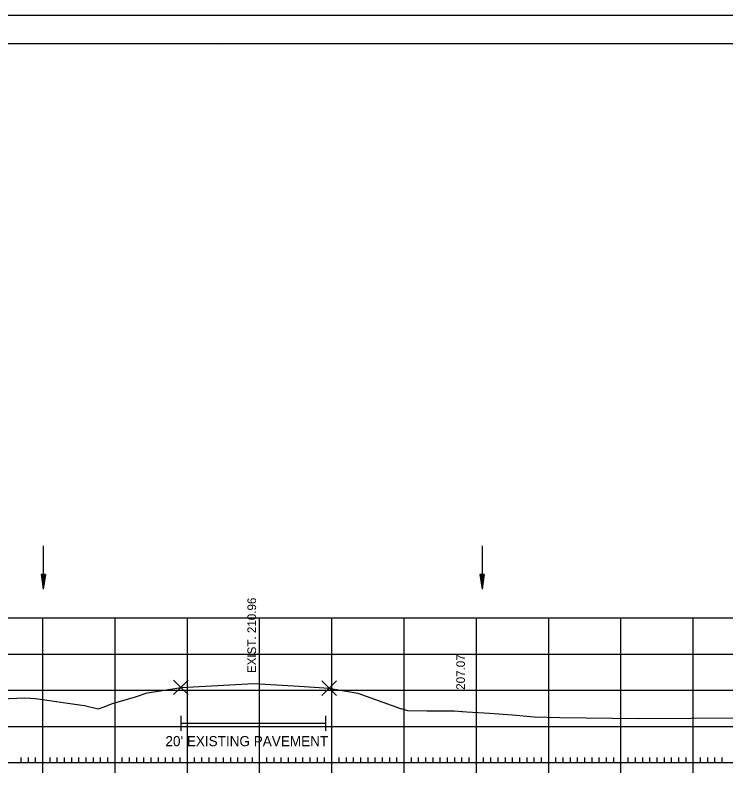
# Model space of a CAD drawing. Extents: x 1312042 to 1371461, y 379929 to 1834241.
# Drawn here: x 1371264.5 to 1371362.8, y 380250.2 to 380355.6 of the extents above; entities that cross this region are included whole.
import ezdxf

# ---------------------------------------------------------------- set-up
doc = ezdxf.new("R2010")
doc.units = 0
for name, color, linetype in [('Default', 7, 'Continuous'), ('R_Axis', 7, 'Continuous'), ('R_Axis Annot', 7, 'Continuous'), ('R_Border', 7, 'Continuous'), ('R_Exist Surface', 7, 'Continuous'), ('R_Grid', 7, 'Continuous'), ('R_No Plot', 7, 'Continuous'), ('R_Water Annot', 7, 'Continuous'), ('R_Xsect Elev', 7, 'Continuous')]:
    doc.layers.add(name, color=color, linetype=linetype)

msp = doc.modelspace()

# ---------------------------------------------------------------- linework, layer by layer
at = {"layer": 'Default'}
for p, q in [((1371287.38, 380258.72), (1371287.38, 380256.66)), ((1371307.38, 380258.72), (1371307.38, 380256.66)), ((1371287.38, 380257.69), (1371307.38, 380257.69))]:
    msp.add_line(p, q, dxfattribs=at)
at = {"layer": 'R_Axis'}
for p, q in [((1371268.28, 380250.85), (1371268.28, 380253.65)), ((1371278.28, 380250.85), (1371278.28, 380253.65)), ((1371288.28, 380250.85), (1371288.28, 380253.65)), ((1371298.28, 380250.85), (1371298.28, 380253.65)), ((1371308.28, 380250.85), (1371308.28, 380253.65)), ((1371318.28, 380250.85), (1371318.28, 380253.65)), ((1371328.28, 380250.85), (1371328.28, 380253.65)), ((1371338.28, 380250.85), (1371338.28, 380253.65)), ((1371348.28, 380250.85), (1371348.28, 380253.65)), ((1371358.28, 380250.85), (1371358.28, 380253.65)), ((1371158.28, 380252.25), (1371438.28, 380252.25)), ((1371265.28, 380252.25), (1371265.28, 380252.95)), ((1371266.28, 380252.25), (1371266.28, 380252.95)), ((1371267.28, 380252.25), (1371267.28, 380252.95)), ((1371269.28, 380252.25), (1371269.28, 380252.95)), ((1371270.28, 380252.25), (1371270.28, 380252.95)), ((1371271.28, 380252.25), (1371271.28, 380252.95)), ((1371272.28, 380252.25), (1371272.28, 380252.95)), ((1371273.28, 380252.25), (1371273.28, 380252.95)), ((1371274.28, 380252.25), (1371274.28, 380252.95)), ((1371275.28, 380252.25), (1371275.28, 380252.95)), ((1371276.28, 380252.25), (1371276.28, 380252.95)), ((1371277.28, 380252.25), (1371277.28, 380252.95)), ((1371279.28, 380252.25), (1371279.28, 380252.95)), ((1371280.28, 380252.25), (1371280.28, 380252.95)), ((1371281.28, 380252.25), (1371281.28, 380252.95)), ((1371282.28, 380252.25), (1371282.28, 380252.95)), ((1371283.28, 380252.25), (1371283.28, 380252.95)), ((1371284.28, 380252.25), (1371284.28, 380252.95)), ((1371285.28, 380252.25), (1371285.28, 380252.95)), ((1371286.28, 380252.25), (1371286.28, 380252.95)), ((1371287.28, 380252.25), (1371287.28, 380252.95)), ((1371289.28, 380252.25), (1371289.28, 380252.95)), ((1371290.28, 380252.25), (1371290.28, 380252.95)), ((1371291.28, 380252.25), (1371291.28, 380252.95)), ((1371292.28, 380252.25), (1371292.28, 380252.95)), ((1371293.28, 380252.25), (1371293.28, 380252.95)), ((1371294.28, 380252.25), (1371294.28, 380252.95)), ((1371295.28, 380252.25), (1371295.28, 380252.95)), ((1371296.28, 380252.25), (1371296.28, 380252.95)), ((1371297.28, 380252.25), (1371297.28, 380252.95)), ((1371299.28, 380252.25), (1371299.28, 380252.95)), ((1371300.28, 380252.25), (1371300.28, 380252.95)), ((1371301.28, 380252.25), (1371301.28, 380252.95)), ((1371302.28, 380252.25), (1371302.28, 380252.95)), ((1371303.28, 380252.25), (1371303.28, 380252.95)), ((1371304.28, 380252.25), (1371304.28, 380252.95)), ((1371305.28, 380252.25), (1371305.28, 380252.95)), ((1371306.28, 380252.25), (1371306.28, 380252.95)), ((1371307.28, 380252.25), (1371307.28, 380252.95)), ((1371309.28, 380252.25), (1371309.28, 380252.95)), ((1371310.28, 380252.25), (1371310.28, 380252.95)), ((1371311.28, 380252.25), (1371311.28, 380252.95)), ((1371312.28, 380252.25), (1371312.28, 380252.95)), ((1371313.28, 380252.25), (1371313.28, 380252.95)), ((1371314.28, 380252.25), (1371314.28, 380252.95)), ((1371315.28, 380252.25), (1371315.28, 380252.95)), ((1371316.28, 380252.25), (1371316.28, 380252.95)), ((1371317.28, 380252.25), (1371317.28, 380252.95)), ((1371319.28, 380252.25), (1371319.28, 380252.95)), ((1371320.28, 380252.25), (1371320.28, 380252.95)), ((1371321.28, 380252.25), (1371321.28, 380252.95)), ((1371322.28, 380252.25), (1371322.28, 380252.95)), ((1371323.28, 380252.25), (1371323.28, 380252.95)), ((1371324.28, 380252.25), (1371324.28, 380252.95)), ((1371325.28, 380252.25), (1371325.28, 380252.95)), ((1371326.28, 380252.25), (1371326.28, 380252.95)), ((1371327.28, 380252.25), (1371327.28, 380252.95)), ((1371329.28, 380252.25), (1371329.28, 380252.95)), ((1371330.28, 380252.25), (1371330.28, 380252.95)), ((1371331.28, 380252.25), (1371331.28, 380252.95)), ((1371332.28, 380252.25), (1371332.28, 380252.95)), ((1371333.28, 380252.25), (1371333.28, 380252.95)), ((1371334.28, 380252.25), (1371334.28, 380252.95)), ((1371335.28, 380252.25), (1371335.28, 380252.95)), ((1371336.28, 380252.25), (1371336.28, 380252.95)), ((1371337.28, 380252.25), (1371337.28, 380252.95)), ((1371339.28, 380252.25), (1371339.28, 380252.95)), ((1371340.28, 380252.25), (1371340.28, 380252.95)), ((1371341.28, 380252.25), (1371341.28, 380252.95)), ((1371342.28, 380252.25), (1371342.28, 380252.95)), ((1371343.28, 380252.25), (1371343.28, 380252.95)), ((1371344.28, 380252.25), (1371344.28, 380252.95)), ((1371345.28, 380252.25), (1371345.28, 380252.95)), ((1371346.28, 380252.25), (1371346.28, 380252.95)), ((1371347.28, 380252.25), (1371347.28, 380252.95)), ((1371349.28, 380252.25), (1371349.28, 380252.95)), ((1371350.28, 380252.25), (1371350.28, 380252.95)), ((1371351.28, 380252.25), (1371351.28, 380252.95)), ((1371352.28, 380252.25), (1371352.28, 380252.95)), ((1371353.28, 380252.25), (1371353.28, 380252.95)), ((1371354.28, 380252.25), (1371354.28, 380252.95)), ((1371355.28, 380252.25), (1371355.28, 380252.95)), ((1371356.28, 380252.25), (1371356.28, 380252.95)), ((1371357.28, 380252.25), (1371357.28, 380252.95)), ((1371359.28, 380252.25), (1371359.28, 380252.95)), ((1371360.28, 380252.25), (1371360.28, 380252.95)), ((1371361.28, 380252.25), (1371361.28, 380252.95)), ((1371362.28, 380252.25), (1371362.28, 380252.95))]:
    msp.add_line(p, q, dxfattribs=at)
at = {"layer": 'R_Border'}
for p, q in [((1371140.28, 380351.71), (1371456.46, 380351.71)), ((1371292.8, 380351.45), (1371292.8, 380351.45)), ((1371292.8, 380351.45), (1371292.8, 380351.45))]:
    msp.add_line(p, q, dxfattribs=at)
at = {"layer": 'R_Exist Surface'}
msp.add_lwpolyline([(1371230.56, 380259.75), (1371265.8, 380261.22), (1371267.25, 380261.11), (1371273.69, 380260.18), (1371274.05, 380260.16), (1371275.96, 380259.71), (1371276.63, 380259.92), (1371277.94, 380260.41), (1371281.1, 380261.37), (1371282.72, 380261.91), (1371284.57, 380262.19), (1371287.38, 380262.65), (1371293.33, 380262.96), (1371297.5, 380263.21), (1371303.77, 380262.81), (1371307.9, 380262.55), (1371308.65, 380262.4), (1371311.89, 380261.86), (1371317.65, 380259.8), (1371318.75, 380259.44), (1371321.43, 380259.4), (1371325.19, 380259.41), (1371326.94, 380259.26), (1371330.1, 380259.1), (1371333.28, 380258.86), (1371336.27, 380258.6), (1371339.83, 380258.5), (1371350.74, 380258.35), (1371365.24, 380258.45)], dxfattribs=at)
at = {"layer": 'R_Grid'}
for p, q in [((1371158.28, 380272.25), (1371438.28, 380272.25)), ((1371268.28, 380252.25), (1371268.28, 380272.25)), ((1371278.28, 380252.25), (1371278.28, 380272.25)), ((1371288.28, 380252.25), (1371288.28, 380272.25)), ((1371298.28, 380252.25), (1371298.28, 380272.25)), ((1371308.28, 380252.25), (1371308.28, 380272.25)), ((1371318.28, 380252.25), (1371318.28, 380272.25)), ((1371328.28, 380252.25), (1371328.28, 380272.25)), ((1371338.28, 380252.25), (1371338.28, 380272.25)), ((1371348.28, 380252.25), (1371348.28, 380272.25)), ((1371358.28, 380252.25), (1371358.28, 380272.25)), ((1371158.28, 380267.25), (1371438.28, 380267.25)), ((1371158.28, 380262.25), (1371438.28, 380262.25)), ((1371158.28, 380257.25), (1371438.28, 380257.25)), ((1371158.28, 380252.25), (1371438.28, 380252.25))]:
    msp.add_line(p, q, dxfattribs=at)
at = {"layer": 'R_No Plot'}
msp.add_line((1371127.88, 380355.6), (1371461.21, 380355.6), dxfattribs=at)
for points in [[(1371127.87, 380355.6), (1371461.21, 380355.6), (1371461.21, 380142.26), (1371127.87, 380142.26)], [(1371374.2, 380351.71), (1371374.2, 380341.83), (1371409.93, 380341.83), (1371409.93, 380338.91), (1371433.13, 380338.91), (1371433.13, 380314.57), (1371456.46, 380314.57), (1371456.46, 380146.25), (1371140.28, 380146.25), (1371140.28, 380351.71)], [(1371326.24, 380259.32), (1371326.29, 380259.32), (1371326.28, 380259.31)]]:
    msp.add_lwpolyline(points, close=True, dxfattribs=at)
for points in [[(1371287.38, 380262.65), (1371286.38, 380263.65), (1371287.38, 380262.65), (1371286.38, 380261.65), (1371287.38, 380262.65), (1371288.38, 380261.65), (1371287.38, 380262.65), (1371288.38, 380263.65)], [(1371307.9, 380262.55), (1371306.9, 380263.55), (1371307.9, 380262.55), (1371306.9, 380261.55), (1371307.9, 380262.55), (1371308.9, 380261.55), (1371307.9, 380262.55), (1371308.9, 380263.55)]]:
    msp.add_lwpolyline(points, dxfattribs=at)
at = {"layer": 'R_Water Annot'}
for p, q in [((1371268.34, 380282.25), (1371268.34, 380276.25)), ((1371329.05, 380282.25), (1371329.05, 380276.25)), ((1371268.04, 380278.25), (1371268.34, 380276.25)), ((1371268.64, 380278.25), (1371268.04, 380278.25)), ((1371268.09, 380278.25), (1371268.34, 380276.59)), ((1371268.14, 380278.25), (1371268.34, 380276.93)), ((1371268.19, 380278.25), (1371268.34, 380277.26)), ((1371268.25, 380278.25), (1371268.34, 380277.6)), ((1371268.3, 380278.25), (1371268.34, 380277.94)), ((1371268.64, 380278.25), (1371268.34, 380276.25)), ((1371268.44, 380278.25), (1371268.34, 380277.6)), ((1371268.54, 380278.25), (1371268.34, 380276.93)), ((1371268.59, 380278.25), (1371268.34, 380276.59)), ((1371268.49, 380278.25), (1371268.34, 380277.26)), ((1371268.39, 380278.25), (1371268.34, 380277.94)), ((1371328.75, 380278.25), (1371329.05, 380276.25)), ((1371329.35, 380278.25), (1371328.75, 380278.25)), ((1371328.8, 380278.25), (1371329.05, 380276.59)), ((1371328.85, 380278.25), (1371329.05, 380276.93)), ((1371328.9, 380278.25), (1371329.05, 380277.26)), ((1371328.95, 380278.25), (1371329.05, 380277.6)), ((1371329, 380278.25), (1371329.05, 380277.94)), ((1371329.35, 380278.25), (1371329.05, 380276.25)), ((1371329.15, 380278.25), (1371329.05, 380277.6)), ((1371329.25, 380278.25), (1371329.05, 380276.93)), ((1371329.3, 380278.25), (1371329.05, 380276.59)), ((1371329.2, 380278.25), (1371329.05, 380277.26)), ((1371329.1, 380278.25), (1371329.05, 380277.94))]:
    msp.add_line(p, q, dxfattribs=at)

# ---------------------------------------------------------------- texts
at = {"layer": 'R_Axis Annot'}
msp.add_text("20' EXISTING PAVEMENT", height=1.4, dxfattribs=at).set_placement((1371285.25, 380254.52))
at = {"layer": 'R_Xsect Elev'}
for s, p in [('EXIST. 210.96', (1371297.79, 380264.63)), ('207.07', (1371326.69, 380262.32))]:
    msp.add_text(s, height=1.2, rotation=90, dxfattribs=at).set_placement(p)

doc.saveas('drawing.dxf')
